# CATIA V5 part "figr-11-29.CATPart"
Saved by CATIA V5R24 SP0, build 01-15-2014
Part number: Part1
Bounding box of the stored display mesh (mm): x -52 to 53, y -75.374 to 75.374, z 0 to 37.54
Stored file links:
  D:\KAVITA\CATIA V5-6R2014 Project_ Kavita\CATIA V5-6R2014_partfiles\Partfiles\c11_catia_v5-6r2014_prt\figr-11-29.CATPart
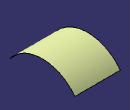
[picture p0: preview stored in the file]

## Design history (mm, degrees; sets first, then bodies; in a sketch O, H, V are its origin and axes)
Set1
  Extrude1: Element1 Sketch1, Lim1 53, Lim2 52, Direction yz-plane
Body1 (main body)
  Sketch1 on yz-plane, origin (0, 0, 0), H (0, 1, 0), V (0, 0, 1)
    arc A1 centre (0, -56.4477) radius 94.1675 from (-75.3736, 0) to (75.3736, 0) cw
    point P1 (0, -56.4477)
    point P2 (-75.3736, 0)
    point P3 (75.3736, 0)
    point P4 (0, 37.7198)
    coincidence: P2 H, P3 H, A1 P4, P4 V, P1 V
